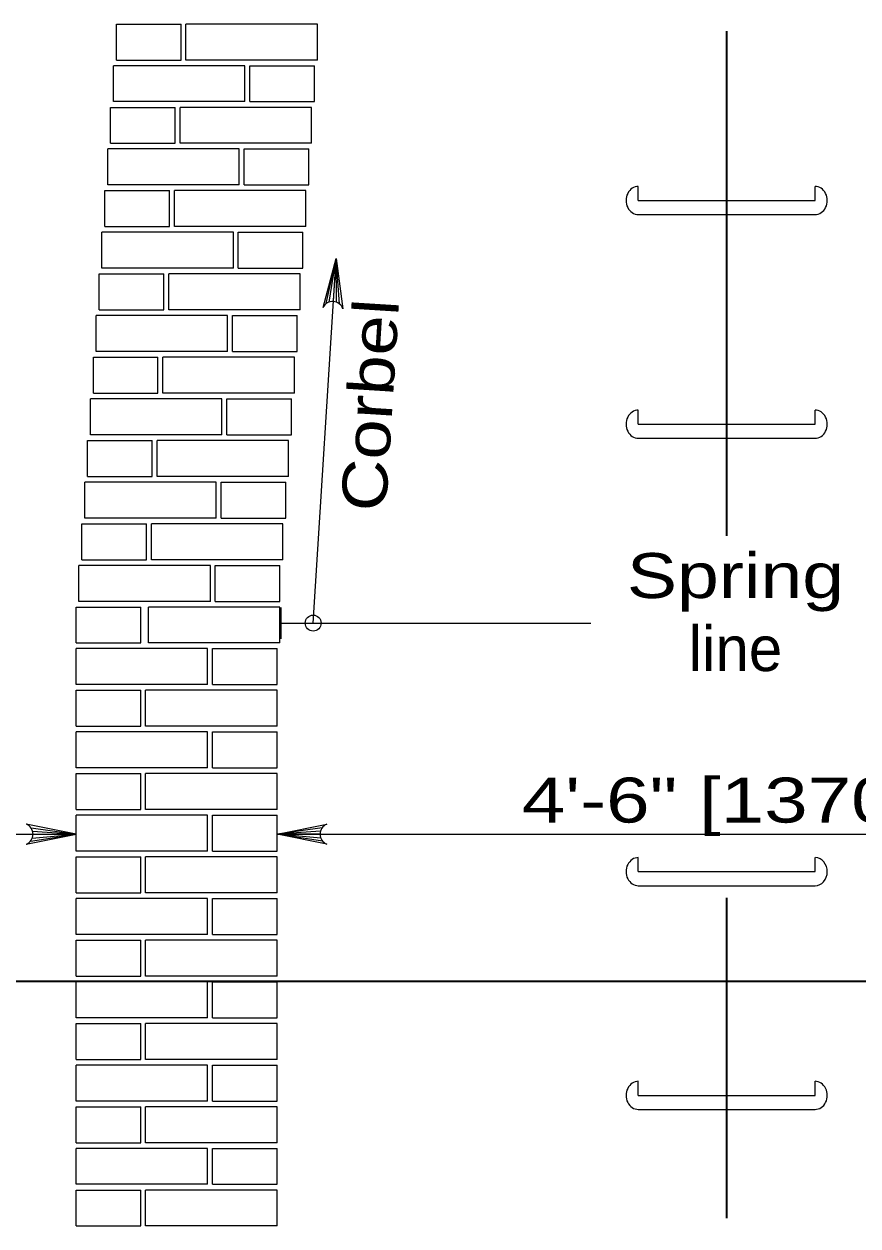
# Model space of a CAD drawing. Extents: x 750.7 to 784.7, y 860.1 to 882.1.
# Drawn here: x 753.818 to 756.786, y 865.564 to 869.843 of the extents above; entities that cross this region are included whole.
import ezdxf
from ezdxf.enums import TextEntityAlignment as Align

# ---------------------------------------------------------------- set-up
doc = ezdxf.new("R2010")
doc.units = 0
doc.header["$LTSCALE"] = 0.064
doc.layers.add('1', color=7, linetype='Continuous', lineweight=13)

msp = doc.modelspace()

# ---------------------------------------------------------------- linework, layer by layer
at = {"layer": '1', "lineweight": 25}
for p, q in [((754.3765, 869.71517), (754.3765, 869.84325)), ((754.14633, 869.71517), (754.3765, 869.71517)), ((754.8515, 869.56692), (754.8515, 869.69492)), ((754.62142, 869.56692), (754.8515, 869.56692)), ((754.356, 869.41867), (754.356, 869.54667)), ((754.12583, 869.41867), (754.356, 869.41867)), ((754.831, 869.27033), (754.831, 869.39842)), ((754.60092, 869.27033), (754.831, 869.27033)), ((754.3355, 869.12208), (754.3355, 869.25017)), ((754.10533, 869.12208), (754.3355, 869.12208)), ((754.8105, 868.97383), (754.8105, 869.10192)), ((754.31492, 868.82558), (754.31492, 868.95358)), ((754.58033, 868.97383), (754.8105, 868.97383)), ((754.08483, 868.82558), (754.31492, 868.82558)), ((754.79, 868.67733), (754.79, 868.80533)), ((754.29442, 868.52908), (754.29442, 868.65708)), ((754.55983, 868.67733), (754.79, 868.67733)), ((754.06433, 868.52908), (754.29442, 868.52908)), ((754.7695, 868.38075), (754.7695, 868.50883)), ((754.27392, 868.2325), (754.27392, 868.36058)), ((754.53933, 868.38075), (754.7695, 868.38075)), ((754.04383, 868.2325), (754.27392, 868.2325)), ((754.749, 868.08425), (754.749, 868.21225)), ((754.25342, 867.936), (754.25342, 868.064)), ((754.51883, 868.08425), (754.749, 868.08425)), ((754.02325, 867.936), (754.25342, 867.936)), ((754.72842, 867.78767), (754.72842, 867.91575)), ((754.23292, 867.63942), (754.23292, 867.7675)), ((754.49833, 867.78767), (754.72842, 867.78767)), ((754.73342, 867.65467), (754.73342, 867.766)), ((754.00283, 867.63942), (754.23292, 867.63942)), ((754.71817, 867.49117), (754.71817, 867.61925)), ((754.23292, 867.34292), (754.23292, 867.47092)), ((754.48808, 867.49117), (754.71817, 867.49117)), ((754.00283, 867.34292), (754.23292, 867.34292)), ((754.71817, 867.19467), (754.71817, 867.32267)), ((754.23292, 867.04633), (754.23292, 867.17442)), ((754.48808, 867.19467), (754.71817, 867.19467)), ((754.00283, 867.04633), (754.23292, 867.04633)), ((754.71817, 866.89808), (754.71817, 867.02617)), ((754.23292, 866.74983), (754.23292, 866.87792)), ((754.48808, 866.89808), (754.71817, 866.89808)), ((754.00283, 866.74983), (754.23292, 866.74983)), ((754.71817, 866.60158), (754.71817, 866.72967)), ((754.48808, 866.60158), (754.71817, 866.60158)), ((754.23292, 866.45333), (754.23292, 866.58133)), ((754.00283, 866.45333), (754.23292, 866.45333)), ((754.71817, 866.30508), (754.71817, 866.43308)), ((754.48808, 866.30508), (754.71817, 866.30508)), ((754.23292, 866.15675), (754.23292, 866.28483)), ((754.00283, 866.15675), (754.23292, 866.15675)), ((754.71817, 866.0085), (754.71817, 866.13658)), ((754.48808, 866.0085), (754.71817, 866.0085)), ((754.23292, 865.86025), (754.23292, 865.98833)), ((754.00283, 865.86025), (754.23292, 865.86025)), ((754.71817, 865.712), (754.71817, 865.84)), ((754.48808, 865.712), (754.71817, 865.712)), ((754.23292, 865.56375), (754.23292, 865.69175)), ((754.00283, 865.56375), (754.23292, 865.56375))]:
    msp.add_line(p, q, dxfattribs=at)
at = {"layer": '1', "lineweight": 35}
for p, q in [((756.31867, 868.02117), (756.31867, 869.81733)), ((756.31867, 865.59108), (756.31867, 866.732)), ((758.92867, 866.43383), (753.73875, 866.43375))]:
    msp.add_line(p, q, dxfattribs=at)
at = {"layer": '1'}
for p, q in [((756.00417, 869.21508), (756.00417, 869.26517)), ((756.63317, 869.21508), (756.63308, 869.26517)), ((756.00417, 869.21508), (756.63317, 869.21508)), ((756.00417, 869.16492), (756.63317, 869.16492)), ((754.84675, 867.71033), (754.92833, 869.00817)), ((754.89342, 868.84783), (754.92833, 869.00817)), ((754.90417, 868.85333), (754.92833, 869.00817)), ((754.91875, 868.85525), (754.92833, 869.00817)), ((754.92992, 868.85292), (754.92833, 869.00817)), ((754.94067, 868.84675), (754.92833, 869.00817)), ((756.00417, 868.41842), (756.00417, 868.46858)), ((756.63317, 868.41842), (756.63308, 868.46858)), ((756.00417, 868.41842), (756.63317, 868.41842)), ((756.00417, 868.36833), (756.63317, 868.36833)), ((754.73342, 867.71033), (755.83483, 867.71033)), ((753.69892, 866.9585), (754.00283, 866.9585)), ((753.84058, 866.93375), (754.00283, 866.9585)), ((753.8425, 866.98092), (754.00283, 866.9585)), ((753.84675, 866.94408), (754.00283, 866.9585)), ((753.84792, 866.96983), (754.00283, 866.9585)), ((753.84958, 866.9585), (754.00283, 866.9585)), ((754.8785, 866.98092), (754.71817, 866.9585)), ((754.87308, 866.96983), (754.71817, 866.9585)), ((754.71817, 866.9585), (756.67608, 866.9585)), ((754.87142, 866.9585), (754.71817, 866.9585)), ((754.87425, 866.94408), (754.71817, 866.9585)), ((754.88042, 866.93375), (754.71817, 866.9585)), ((756.67608, 866.9585), (757.91908, 866.9585)), ((756.00417, 866.82525), (756.00417, 866.87542)), ((756.63317, 866.82525), (756.63308, 866.87542)), ((756.00417, 866.82525), (756.63317, 866.82525)), ((756.00417, 866.77517), (756.63317, 866.77517)), ((756.00417, 866.02867), (756.00417, 866.07883)), ((756.63317, 866.02867), (756.63308, 866.07883)), ((756.00417, 866.02867), (756.63317, 866.02867)), ((756.00417, 865.97858), (756.63317, 865.97858))]:
    msp.add_line(p, q, dxfattribs=at)
at = {"layer": '1', "lineweight": 25}
for points in [[(754.14633, 869.71517), (754.14633, 869.84325), (754.3765, 869.84325)], [(754.86175, 869.71517), (754.86175, 869.84325), (754.39408, 869.84325)], [(754.86175, 869.71517), (754.39408, 869.71517), (754.39408, 869.84325)], [(754.60383, 869.56692), (754.60383, 869.69492), (754.13608, 869.69492)], [(754.60383, 869.56692), (754.13608, 869.56692), (754.13608, 869.69492)], [(754.62142, 869.56692), (754.62142, 869.69492), (754.8515, 869.69492)], [(754.12583, 869.41867), (754.12583, 869.54667), (754.356, 869.54667)], [(754.84125, 869.41858), (754.84125, 869.54667), (754.37358, 869.54667)], [(754.84125, 869.41858), (754.37358, 869.41858), (754.37358, 869.54667)], [(754.58325, 869.27033), (754.58325, 869.39842), (754.11558, 869.39842)], [(754.58325, 869.27033), (754.11558, 869.27033), (754.11558, 869.39842)], [(754.60092, 869.27033), (754.60092, 869.39842), (754.831, 869.39842)], [(754.10533, 869.12208), (754.10533, 869.25017), (754.3355, 869.25017)], [(754.82075, 869.12208), (754.82075, 869.25017), (754.35308, 869.25017)], [(754.82075, 869.12208), (754.35308, 869.12208), (754.35308, 869.25017)], [(754.56275, 868.97383), (754.56275, 869.10192), (754.09508, 869.10192)], [(754.56275, 868.97383), (754.09508, 868.97383), (754.09508, 869.10192)], [(754.58033, 868.97383), (754.58033, 869.10192), (754.8105, 869.10192)], [(754.08483, 868.82558), (754.08483, 868.95358), (754.31492, 868.95358)], [(754.80025, 868.82558), (754.80025, 868.95358), (754.33258, 868.95358)], [(754.80025, 868.82558), (754.33258, 868.82558), (754.33258, 868.95358)], [(754.54225, 868.67733), (754.54225, 868.80533), (754.07458, 868.80533)], [(754.54225, 868.67733), (754.07458, 868.67733), (754.07458, 868.80533)], [(754.55983, 868.67733), (754.55983, 868.80533), (754.79, 868.80533)], [(754.06433, 868.52908), (754.06433, 868.65708), (754.29442, 868.65708)], [(754.77975, 868.529), (754.77975, 868.65708), (754.31208, 868.65708)], [(754.77975, 868.529), (754.31208, 868.529), (754.31208, 868.65708)], [(754.52175, 868.38075), (754.52175, 868.50883), (754.05408, 868.50883)], [(754.52175, 868.38075), (754.05408, 868.38075), (754.05408, 868.50883)], [(754.53933, 868.38075), (754.53933, 868.50883), (754.7695, 868.50883)], [(754.04383, 868.2325), (754.04383, 868.36058), (754.27392, 868.36058)], [(754.75925, 868.2325), (754.75925, 868.36058), (754.2915, 868.36058)], [(754.75925, 868.2325), (754.2915, 868.2325), (754.2915, 868.36058)], [(754.50125, 868.08425), (754.50125, 868.21233), (754.0335, 868.21233)], [(754.50125, 868.08425), (754.0335, 868.08425), (754.0335, 868.21233)], [(754.51883, 868.08425), (754.51883, 868.21225), (754.749, 868.21225)], [(754.02325, 867.936), (754.02325, 868.064), (754.25342, 868.064)], [(754.73867, 867.936), (754.73867, 868.064), (754.271, 868.064)], [(754.73867, 867.936), (754.271, 867.936), (754.271, 868.064)], [(754.48075, 867.78767), (754.48075, 867.91575), (754.013, 867.91575)], [(754.48075, 867.78767), (754.013, 867.78767), (754.013, 867.91575)], [(754.49833, 867.78767), (754.49833, 867.91575), (754.72842, 867.91575)], [(754.00283, 867.63942), (754.00283, 867.7675), (754.23292, 867.7675)], [(754.72842, 867.63942), (754.72842, 867.7675), (754.26075, 867.7675)], [(754.72842, 867.63942), (754.26075, 867.63942), (754.26075, 867.7675)], [(754.47042, 867.49117), (754.47042, 867.61925), (754.00275, 867.61925)], [(754.47042, 867.49117), (754.00275, 867.49117), (754.00275, 867.61925)], [(754.48808, 867.49117), (754.48808, 867.61925), (754.71817, 867.61925)], [(754.00283, 867.34292), (754.00283, 867.47092), (754.23292, 867.47092)], [(754.71817, 867.34292), (754.71817, 867.47092), (754.2505, 867.47092)], [(754.71817, 867.34292), (754.2505, 867.34292), (754.2505, 867.47092)], [(754.47042, 867.19467), (754.47042, 867.32267), (754.00275, 867.32267)], [(754.47042, 867.19467), (754.00275, 867.19467), (754.00275, 867.32267)], [(754.48808, 867.19467), (754.48808, 867.32267), (754.71817, 867.32267)], [(754.00283, 867.04633), (754.00283, 867.17442), (754.23292, 867.17442)], [(754.71817, 867.04633), (754.71817, 867.17442), (754.2505, 867.17442)], [(754.71817, 867.04633), (754.2505, 867.04633), (754.2505, 867.17442)], [(754.47042, 866.89808), (754.47042, 867.02617), (754.00275, 867.02617)], [(754.47042, 866.89808), (754.00275, 866.89808), (754.00275, 867.02617)], [(754.48808, 866.89808), (754.48808, 867.02617), (754.71817, 867.02617)], [(754.00283, 866.74983), (754.00283, 866.87792), (754.23292, 866.87792)], [(754.71817, 866.74983), (754.71817, 866.87792), (754.2505, 866.87792)], [(754.71817, 866.74983), (754.2505, 866.74983), (754.2505, 866.87792)], [(754.47042, 866.60158), (754.47042, 866.72967), (754.00275, 866.72967)], [(754.47042, 866.60158), (754.00275, 866.60158), (754.00275, 866.72967)], [(754.48808, 866.60158), (754.48808, 866.72967), (754.71817, 866.72967)], [(754.00283, 866.45333), (754.00283, 866.58133), (754.23292, 866.58133)], [(754.71817, 866.45333), (754.71817, 866.58133), (754.2505, 866.58133)], [(754.71817, 866.45333), (754.2505, 866.45333), (754.2505, 866.58133)], [(754.47042, 866.30508), (754.47042, 866.43308), (754.00275, 866.43308)], [(754.47042, 866.30508), (754.00275, 866.30508), (754.00275, 866.43308)], [(754.48808, 866.30508), (754.48808, 866.43308), (754.71817, 866.43308)], [(754.00283, 866.15675), (754.00283, 866.28483), (754.23292, 866.28483)], [(754.71817, 866.15675), (754.71817, 866.28483), (754.2505, 866.28483)], [(754.71817, 866.15675), (754.2505, 866.15675), (754.2505, 866.28483)], [(754.47042, 866.0085), (754.47042, 866.13658), (754.00275, 866.13658)], [(754.47042, 866.0085), (754.00275, 866.0085), (754.00275, 866.13658)], [(754.48808, 866.0085), (754.48808, 866.13658), (754.71817, 866.13658)], [(754.00283, 865.86025), (754.00283, 865.98833), (754.23292, 865.98833)], [(754.71817, 865.86025), (754.71817, 865.98833), (754.2505, 865.98833)], [(754.71817, 865.86025), (754.2505, 865.86025), (754.2505, 865.98833)], [(754.47042, 865.712), (754.47042, 865.84008), (754.00275, 865.84008)], [(754.47042, 865.712), (754.00275, 865.712), (754.00275, 865.84008)], [(754.48808, 865.712), (754.48808, 865.84), (754.71817, 865.84)], [(754.00283, 865.56375), (754.00283, 865.69175), (754.23292, 865.69175)], [(754.71817, 865.56375), (754.71817, 865.69175), (754.2505, 865.69175)], [(754.71817, 865.56375), (754.2505, 865.56375), (754.2505, 865.69175)]]:
    msp.add_lwpolyline(points, dxfattribs=at)
at = {"layer": '1'}
for points in [[(754.88183, 868.83367), (754.92833, 869.00817), (754.95258, 868.82925)], [(753.82575, 866.92308), (754.00283, 866.9585), (753.82575, 866.99392)], [(754.89525, 866.92308), (754.71817, 866.9585), (754.89525, 866.99392)]]:
    msp.add_lwpolyline(points, dxfattribs=at)
msp.add_circle((754.84675, 867.71035), 0.02833, dxfattribs=at)
for centre, start, end in [((754.91636, 868.81719), 18.49101, 154.31714), ((753.81144, 866.95855), 292.08605, 67.91218), ((754.90957, 866.95855), 112.08782, 247.91395)]:
    msp.add_arc(centre, 0.03822, start, end, dxfattribs=at)
for centre, major_axis, end_param in [((756.00413, 869.21504), (0, 0.05012), 3.1415958), ((756.63317, 869.21504), (0, -0.05012), 3.143156), ((756.00413, 868.41846), (0, 0.05012), 3.1415958), ((756.63317, 868.41846), (0, -0.05012), 3.143156), ((756.00413, 866.82529), (0, 0.05012), 3.1415958), ((756.63317, 866.82529), (0, -0.05012), 3.113657), ((756.00413, 866.02871), (0, 0.05012), 3.1415958), ((756.63317, 866.02871), (0, -0.05012), 3.143156)]:
    msp.add_ellipse(centre, major_axis=major_axis, ratio=0.869565, start_param=0.000003, end_param=end_param, dxfattribs=at)

# ---------------------------------------------------------------- texts
at = {"layer": '1', "width": 1.2}
msp.add_text('Corbel', height=0.16, rotation=86.403, dxfattribs=at).set_placement((755.10533, 868.104))
at = {"layer": '1', "width": 1.25}
msp.add_text('Spring', height=0.16, dxfattribs=at).set_placement((756.35004, 867.7995), align=Align.CENTER)
at = {"layer": '1'}
msp.add_text('line', height=0.16, dxfattribs=at).set_placement((756.35004, 867.5395), align=Align.CENTER)
at = {"layer": '1', "width": 1.3}
msp.add_text('4\'-6" [1370]', height=0.16, dxfattribs=at).set_placement((755.58925, 867.00008))

doc.saveas('drawing.dxf')
